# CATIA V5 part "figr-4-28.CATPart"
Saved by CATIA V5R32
Part number: Part1
Bounding box of the stored display mesh (mm): x -89.975 to 89.975, y -89.975 to 89.975, z 0 to 190
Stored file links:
  D:\PROJECTS\Project 2022\CATIA V5 6R 2022\Resources\Part Files\c04_catia_v5_6r2022_prt\figr-4-28.CATPart
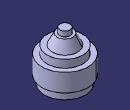
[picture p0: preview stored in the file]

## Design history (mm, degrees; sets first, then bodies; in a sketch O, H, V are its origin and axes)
Set1
  Line1 "Y Axis": stored without definition
  Line2 "Y Axis": stored without definition
  Line3 "X Axis": stored without definition
  Line4 "Z Axis": stored without definition
Body1 (main body)
  Sketch1 on yz-plane, origin (0, 0, 0), H (0, 1, 0), V (0, 0, 1)
    line L1 (0, 0) -> (80, 0)
    line L2 (80, 0) -> (80, 30)
    line L3 (80, 30) -> (90, 30)
    line L4 (90, 30) -> (90, 100)
    line L5 (90, 100) -> (70, 100)
    line L6 (70, 100) -> (70, 130)
    line L7 (70, 130) -> (50, 130)
    line L8 (50, 130) -> (30, 170)
    line L9 (30, 170) -> (20, 170)
    line L10 (20, 170) -> (20, 190)
    line L11 (20, 190) -> (0, 190)
    point P11 (0, 190)
    line L12 (0, 190) -> (0, 0)
    axis line L13 (0, -40) -> (0, 230)
    point P12 (0, -40)
    point P13 (0, 230)
    horizontal: L1 H, L3 H, L5 H, L7 H, L9 H, L11 H
    vertical: L2 V, L4 V, L6 V, L10 V, L12 V, L13 V
    coincidence: P11 V, P12 V, P13 L8
  Shaft1: profile Sketch1, axis Sketch1.L13, angle 360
